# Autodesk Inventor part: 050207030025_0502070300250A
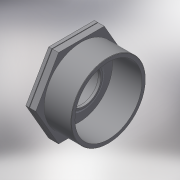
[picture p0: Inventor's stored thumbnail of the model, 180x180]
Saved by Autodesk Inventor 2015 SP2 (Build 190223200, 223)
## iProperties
Created: 2017-05
Part Number: 050207030025_0502070300250A
Material: Generic
Description: PLASSON REDUCING BUSHING 3"-2.1/2"
Document SubType Name: Modeling
Designer: KIM
Density: 1 g/cm^3
Appearance: Default
Author: KIM
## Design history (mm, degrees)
derived "050207.ipt"
feature "Solid1::050207.ipt"
tag "TaggingFeature1"
body "Solid1"
other parameters: "d1" = 87.884, "d5" = 32, "d8" = 0.48, "d12" = 0, "d15" = 48, "d19" = 0, "d30" = 9.6, "d31" = 4.8, "d33" = 44.845, "d34" = 79.0956, "d36" = 4.5, "d37" = 53.814, "d38" = 31.68, "d39" = 40.3605, "d40" = 3.2, "d41" = 0, "H_" = 48, "R_" = 87.884, "l_2" = 32, "Rp_" = 44.845
